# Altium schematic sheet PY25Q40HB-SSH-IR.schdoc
size 127 x 101 mm
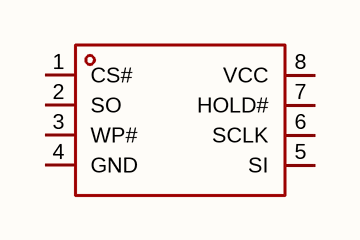
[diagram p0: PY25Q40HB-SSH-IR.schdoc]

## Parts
U?  py25q40hb-ssh-ir  [SOP-8_L4.9-W3.9-P1.27-LS6.0-BL]  (value not drawn)

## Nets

Not connected (* = marked no-connect by the designer): U? 1(CS#) 2(SO) 3(WP#) 4(GND) 5(SI) 6(SCLK) 7(HOLD#) 8(VCC)

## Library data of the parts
U? = py25q40hb-ssh-ir: 接口类型:SPI;存储容量:4Mbit;时钟频率(fc):133MHz;; Manufacturer: PUYA(普冉); AddInBom: yes; ModelId: 75c24a7891ee4dd6bdac16a7163ff87e; ModelName: SOP-8_L4.9-W3.9-P1.27-LS6.0-BL-1; ModelTransform: 192.913,236.22,0,0,0,0,-0.393,2.749,0; Interface: SPI; Memory Size: 4Mbit; Clock Frequency: 133MHz; Voltage - Supply: 2.3V~3.6V; Standby Supply Current: 15uA; Program / Erase Cycles: 100000次; Page Programming Time (Tpp): 500us; Block Erase Time(tBE): 150ms; Data Retention - TDR (Year): 20年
